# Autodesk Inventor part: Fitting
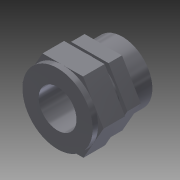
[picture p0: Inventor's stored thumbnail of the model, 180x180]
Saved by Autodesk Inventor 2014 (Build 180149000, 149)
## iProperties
Company: Autodesk, Inc.
Shininess: 64.0
Length Units: 11272
Angle Units: 11279
Time Units: 11290
Mass Units: 11286
Length Display Precision: 3
Angle Display Precision: 2
Compacted: True
Part Number: Fitting
Document SubType Name: Modeling
Created: 2003-10
Designer: Autodesk, Inc.
Manufacturer: Standard
Standards Organization: Custom
Density: 8.03 g/cm^3
Material: Stainless Steel, Austenitic
Mass: 199.701 g
Surface Area: 108.154 cm^2
Volume: 24.8694 cm^3
Appearance: Metal-Steel (Polished)
Density: 0.0
Volumn: 0.0
Area: 0.0
PropertySet Name: Model Information
Control State: 0
Master: False
Checked Out: False
Author: Autodesk, Inc.
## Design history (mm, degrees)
sketch "Sketch1"
  geometry: C1 r 15.081 at (-12.357, 0); C2 r 17.619 at (-12.357, 0)
  constraints: 2 centre point, 1 coincident
extrude "Extrusion1" new body sketch "Sketch1" distance "d0" = 11.1252; taper "d1" = 0 deg
sketch "Sketch2"
  geometry: L1 (10.883, 19.116)-(21.997, 0.133); L2 (21.997, 0.133)-(11.113, -18.983); L3 (11.113, -18.983)-(-10.883, -19.116); L4 (-10.883, -19.116)-(-21.997, -0.133); L5 (-21.997, -0.133)-(-11.113, 18.983); L6 (-11.113, 18.983)-(10.883, 19.116); C1 r 15.081 at (0, 0) reference; C2 r 17.619 at (0, 0) reference; 1 further point
  constraints: 12 end point, 1 coincident, 11 other
  dimensions: "d2" = 38.1 distance between parallel lines of L6 L3
extrude "Extrusion2" join sketch "Sketch2" distance "d3" = 7.9502; taper "d4" = 0 deg
sketch "Sketch3"
  geometry: C1 r 15.081 at (0, 0) reference; C2 r 17.619 at (0, 0) reference
extrude "Extrusion3" join sketch "Sketch3" distance "d5" = 3.175; taper "d6" = 0 deg
sketch "Sketch4"
  geometry: L1 (11.79, 20.709)-(23.83, 0.144); L2 (23.83, 0.144)-(12.039, -20.565); L3 (12.039, -20.565)-(-11.79, -20.709); L4 (-11.79, -20.709)-(-23.83, -0.144); L5 (-23.83, -0.144)-(-12.039, 20.565); L6 (-12.039, 20.565)-(11.79, 20.709); L7 (11.113, -18.983)-(-10.883, -19.116) reference; C1 r 11.113 at (0, 0); C2 r 17.619 at (0, 0) reference; 1 further point
  constraints: 12 end point, 1 centre point, 1 coincident, 1 concentric, 1 parallel, 11 other
  dimensions: "d7" = 41.275 distance between parallel lines of L6 L3; "d12" = 22.225 diameter of C1
extrude "Extrusion4" join sketch "Sketch4" distance "d8" = 12.7; taper "d9" = 0 deg
sketch "Sketch5"
  geometry: L1 (-12.039, 20.565)-(11.79, 20.709) reference; C1 r 11.112 at (0, 0) reference; C2 r 20.637 at (0, 0)
  constraints: 1 centre point, 1 coincident, 1 tangent
extrude "Extrusion5" join sketch "Sketch5" distance "d10" = 3.175; taper "d11" = 0 deg
body "Solid1"
